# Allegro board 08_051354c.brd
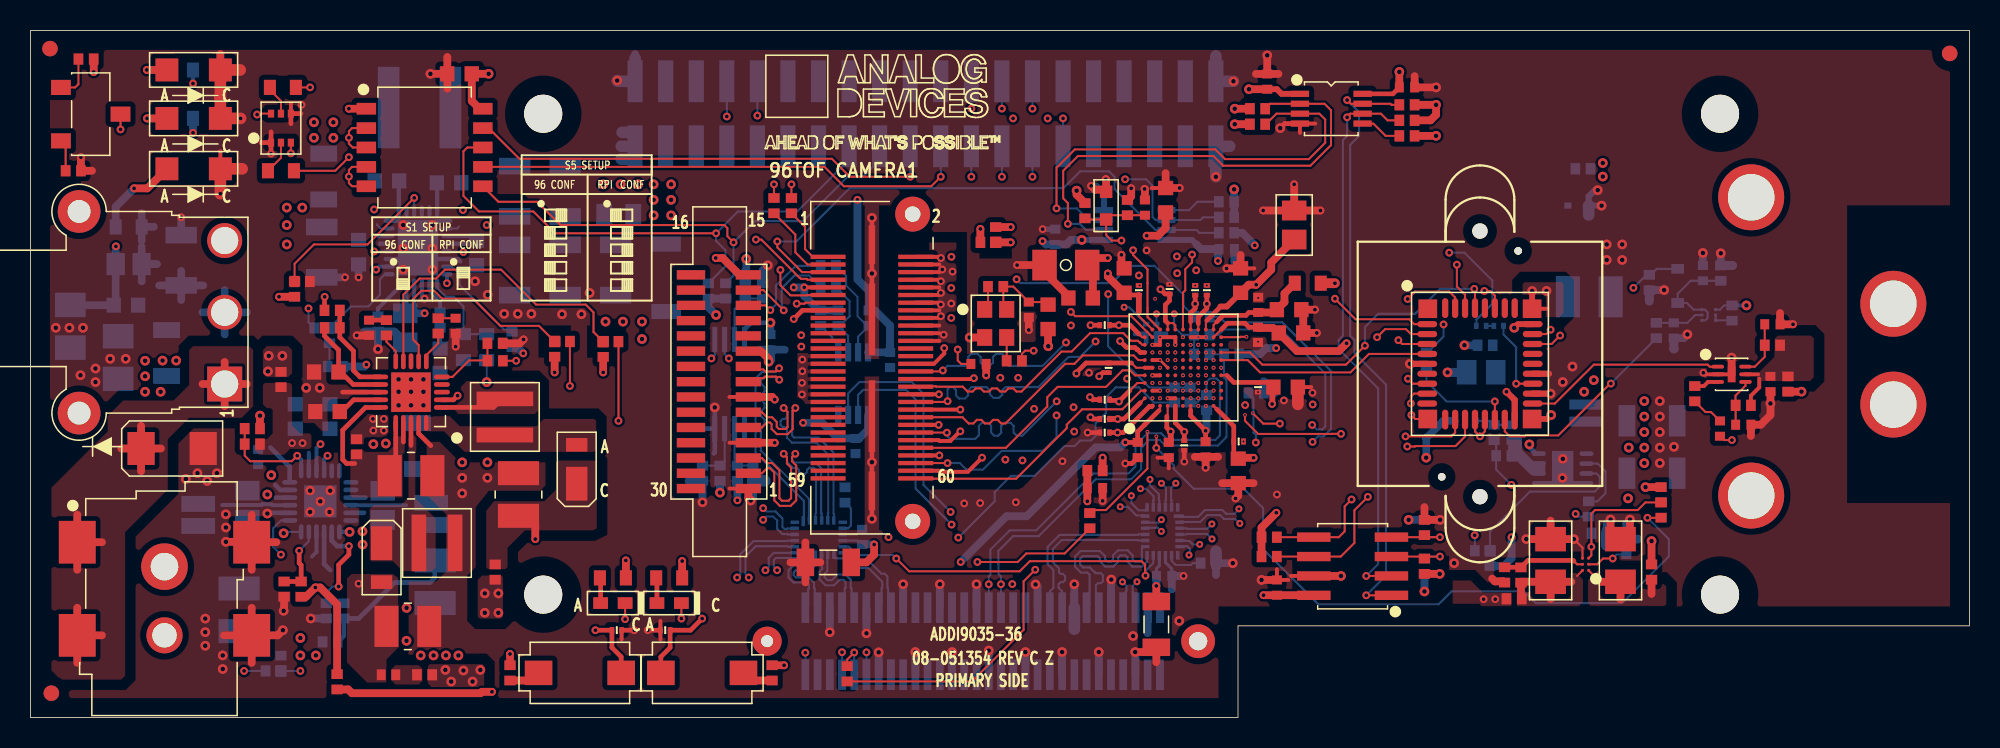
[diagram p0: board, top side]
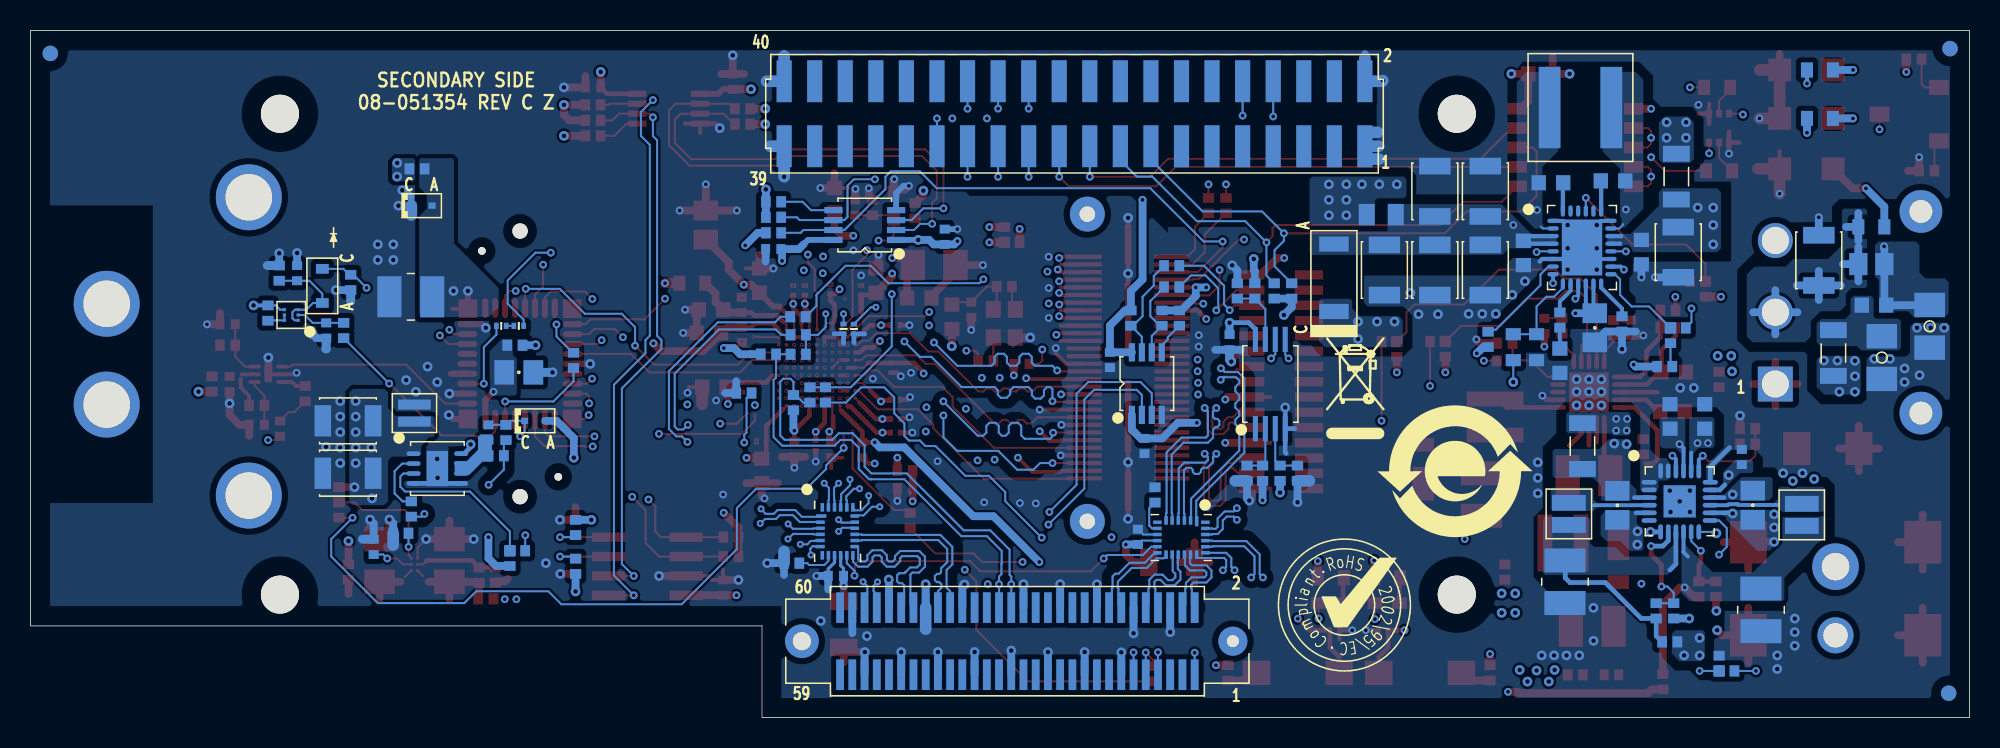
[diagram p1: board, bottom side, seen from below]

Outline 126.86 x 45 mm; copper layers: TOP, L2_GND, L3_SIG, L4_GND, L5_PWR, L6_PWR, L7_GND, L8_SIG, L9_GND, BOTTOM. Coordinates in mm from the lower left corner of the outline.
Outline path: 0,45 126.86,45 126.86,6 79,6 79,0 0,0 0,45

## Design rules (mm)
constraint set DEFAULT: min track width 0.203, pair gap 0.203
net group CLK_DATA_MISIPI: nets CLK_N CLK_P DATA0_N DATA0_P DATA1_N DATA1_P
net group LD1_LD4: nets LD1 LD2 LD3 LD4
net group MIPI_CSI0: nets MIPI_CSI0_CLK_N MIPI_CSI0_CLK_P MIPI_CSI0_DATA0_N MIPI_CSI0_DATA0_P MIPI_CSI0_DATA1_N MIPI_CSI0_DATA1_P
net group MIPI_CSI1: nets MIPI_CSI1_CLK_M MIPI_CSI1_CLK_P MIPI_CSI1_DATA0_M MIPI_CSI1_DATA0_P MIPI_CSI1_DATA1_M MIPI_CSI1_DATA1_P
net group RPI_DATA_P1_CONN: nets RPI_CLKN RPI_CLKP RPI_DATA0N RPI_DATA0P RPI_DATA1N RPI_DATA1P
net group RPI_SRS: nets RPI_SRS_CLKN RPI_SRS_CLKP RPI_SRS_DATA0N RPI_SRS_DATA0P RPI_SRS_DATA1N RPI_SRS_DATA1P
net group TAL1_TAL4: nets TAL1 TAL2 TAL3 TAL4

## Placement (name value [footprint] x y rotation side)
A1  ADA4800ACPZ  [UQFN6_1_6X1_6PAD0_5X1_05]  111.3 22.48 270 top
C1  2.2UF  [C1206]  73.66 6.1 90 top
C2  0.1uF  [C0201]  73.67 25.45 270 bottom
C3  4.7UF  [C0805H60]  14.18 13.91 90 bottom
C4  4.7UF  [C0805H60]  23.04 13.89 270 bottom
C5  0.1UF  [C0402]  65.31 26.71 270 top
C6  4.7uF  [C0603]  74.27 33.88 90 top
C7  0.1UF  [C0402]  69.64 15.03 0 top
C8  0.1uF  [C0201]  72.99 25.45 270 bottom
C9  0.1UF  [C0402]  14.89 17.06 270 bottom
C10  4.7uF  [C0603]  68.7 27.48 180 top
C11  4.7uF  [C0603]  79.17 28.62 90 top
C12  4.7uF  [C0603]  82.47 25.19 0 top
C13  1UF  [C0805H53]  82.68 32.26 90 top
C14  0.1uF  [C0201]  70.53 22.9 270 top
C15  0.1UF  [C0402]  80.31 25.06 270 top
C16  0.1uF  [C0201]  70.28 20.82 180 top
C17  0.1uF  [C0201]  76.96 27.98 90 top
C18  1000PF  [C0402]  107.51 25.35 270 bottom
C19  0.1uF  [C0201]  75.49 17.82 270 top
C20  4.7uF  [C0603]  82.34 26.71 180 top
C21  0.1UF  [C0402]  110.54 18.92 270 top
C22  0.1uF  [C0201]  80.31 21.63 270 top
C23  0.1uF  [C0201]  70.28 18.66 180 top
C24  0.1UF  [C0402]  62.02 23.16 0 top
C25  0.1uF  [C0201]  79.04 18.08 0 top
C26  0.1uF  [C0201]  70.28 25.7 180 top
C27  0.1UF  [C0402]  80.32 27.03 90 top
C28  0.1uF  [C0201]  72.51 27.98 90 top
C29  0.1UF  [C0402]  113.97 25.76 180 top
C30  0.01uF  [C0402]  109.42 29.11 90 bottom
C31  0.1uF  [C0201]  70.28 19.55 180 top
C33  0.1UF  [C0402]  76.88 17.57 270 top
C35  0.1uF  [C0603]  27.38 35.03 180 bottom
C37  4.7uF  [C0805H60]  24.51 25.53 90 bottom
C38  0.1uF  [C0603]  23.32 35.15 180 bottom
C41  10uF  [C1210-2]  24.89 15.84 0 top
C42  22UF  [C1210H106]  9.86 29.95 90 bottom
C43  1UF  [C0603]  19.35 22.63 180 top
C44  22UF  [C1210H106]  106.09 16 0 bottom
C45  1UF  [C0603]  19.59 19.72 90 bottom
C46  1UF  [C0603]  17.32 19.72 90 bottom
C47  10uF  [C1210-2]  26.46 8.89 270 bottom
C48  10uF  [C1210-2]  13.64 7.05 270 bottom
C49  10UF  [C1206H71]  2.6 25.62 90 bottom
C50  10UF  [C1206H71]  5.73 23.58 90 bottom
C51  10uF  [C1210-2]  101.98 27.56 0 bottom
C52  0.1UF  [C0402]  48.41 24.59 270 bottom
C53  1uF  [C0402]  72.44 17.52 90 top
C54  1uF  [C0402]  74.47 17.52 270 top
C55  0.10UF  [C0508H28]  101.74 19.94 90 bottom
C56  10NF  [C0402]  74.17 9.27 180 bottom
C57  1uF  [C0402]  72.91 33.4 270 top
C58  0.1uF  [C0201]  76.2 27.98 90 top
C59  0.033uF  [C0402]  96.9 18.67 90 bottom
C60  0.1uF  [C0201]  74.52 28.06 90 top
C61  10UF  [C1206H71]  67.74 29.64 180 top
C62  0.1UF  [C0402]  113.84 21.84 90 top
C63  0.1UF  [C0402]  80.91 41.66 270 top
C64  22UF  [C1210H106]  106.09 19.43 0 bottom
C65  0.1UF  [C0402]  112.06 19.18 0 top
C66  1UF  [C0603]  19.43 20.04 180 top
C67  0.1uF  [C0603]  28.07 42.16 0 top
C68  0.1UF  [C0402]  90.06 41.27 0 top
C69  0.1UF  [C0402]  81.55 8.51 270 top
C70  0.1UF  [C0402]  67.04 31.49 270 bottom
C71  10uF  [C1210-2]  24.68 5.97 0 top
C72  0.047UF  [C0402]  27.81 25.65 270 top
C73  0.01uF  [C0201]  96.06 25.65 0 bottom
C74  0.047UF  [C0402]  22.14 25.53 270 top
C75  0.1UF  [C0402]  78.26 30.68 0 bottom
C76  4.7UF  [C0805H60]  94.92 22.61 180 bottom
C77  0.01uF  [C0603]  79.02 16.15 90 top
C78  10uF  [C1210-2]  31.92 14.61 90 top
C79  2.2uF  [C1206H37]  104.03 10.29 90 top
C80  1000PF  [C0402]  104.41 11.18 90 bottom
C81  2.2uF  [C1206H37]  99.45 10.29 90 top
C82  0.01uF  [C0603]  82.12 21.64 180 top
C83  0.01uF  [C0603]  71.55 28.62 270 top
C84  0.01uF  [C0201]  38.35 5.71 0 top
C85  0.01uF  [C0201]  41.53 5.71 180 top
C86  2.2UF  [C1206]  52.2 10.16 0 top
C87  10NF  [C0402]  54.41 11.84 270 bottom
C88  0.1UF  [C0402]  53.98 17.78 90 bottom
C89  0.1UF  [C0402]  56.24 23.42 270 bottom
C90  47UF  [C1210H106]  38.28 29.31 270 bottom
C91  560pF  [C0603]  26.8 23.37 90 bottom
C92  47UF  [C1210H106]  34.98 34.47 90 bottom
C93  47UF  [C1210H106]  34.98 29.31 270 bottom
C94  47UF  [C1210H106]  31.67 34.47 90 bottom
C95  47UF  [C1210H106]  31.67 29.31 270 bottom
C96  1UF  [C0603]  29.18 30.43 270 bottom
C97  1UF  [C0603]  21.46 30.48 270 bottom
C98  22UF  [C1210H106]  19.05 30.48 270 bottom
D1  SMAJ5.0A  [DO214AC]  9.26 17.62 0 top
D2  PMEG3030EP,115  [SOD128]  41.58 28.8 90 bottom
D4  RB521S30T1G  [SOD523]  93.85 19.43 180 bottom
D5  1SS355VMTE-17  [SOD323-4]  107.77 28.27 270 bottom
D6  RB521S30T1G  [SOD523]  101.27 33.53 180 bottom
D8  DFLS240-7  [DSML110W70H39]  22.97 10.47 270 top
D9  DFLS240-7  [DSML110W70H39]  35.73 16.26 90 top
DS1  CMD15-21UGC/TR8 (green)  [LED1206]  10.67 35.94 180 top
DS2  CMD15-21UGC/TR8 (green)  [LED1206]  10.67 39.24 180 top
DS3  CMD15-21UGC/TR8 (green)  [LED1206]  10.67 42.42 180 top
DS4  APT1608LVBC/D  [LED0603]  38.1 7.49 180 top
DS5  APT1608LSECK/J3-PRV  [LED0603]  41.78 7.49 180 top
E1  60OHM AT 100MEGHZ  [L0603]  66.57 26.24 270 top
E2  22OHM AT 100MEGHZ  [L0805]  6.42 29.7 180 bottom
E3  30OHM  [L0603]  6.24 27.01 0 bottom
E4  470OHMS AT 100MEGHZ  [L0402]  23.42 2.79 0 top
L1  4.7uH  [LSML250W258H240]  25.45 39.95 180 bottom
L2  1uH  [LSML75W79H39]  10.97 13.27 90 bottom
L3  1uH  [LSML75W79H39]  26.21 13.34 90 bottom
L8  4.7uH  [LSMSQ157H122]  26.59 11.43 180 top
L9  4.7uH  [LSMSQ157H122]  31.03 19.68 270 top
LD_EN1  0  [R0402]  49.78 33.53 90 top
LD_EN2  0  [R0402]  48.64 33.53 90 top
NOREF  -  []  -176.26 -281.43 0 top
NOREF#2  -  []  126.86 6 0 top
NOREF#3  -  []  0 0 0 top
NOREF#4  -  [unnamed#2]  125.57 43.5 90 top
NOREF#5  -  []  281.83 80.52 0 top
NOREF#6  -  []  -125.84 190.5 0 top
NOREF#7  -  []  57.78 56.26 0 top
NOREF#8  -  []  -10.16 55.16 0 top
NOREF#9  -  [unnamed#3]  94.83 23.16 270 top
NOREF#10  -  [unnamed#2]  112.58 34.08 90 top
NOREF#11  -  []  0 0 0 top
NOREF#12  -  []  0 45 0 top
NOREF#13  -  []  0 45 0 top
NOREF#14  -  [unnamed#2]  33.54 8.05 0 top
NOREF#15  -  [unnamed#2]  110.54 8.05 0 top
NOREF#16  -  [unnamed#2]  121.88 20.5 90 top
NOREF#17  -  [unnamed#2]  110.54 39.55 0 top
NOREF#18  -  []  137.02 55.16 0 top
NOREF#19  -  []  79 0 0 top
NOREF#20  -  []  8.76 5.38 0 top
NOREF#21  -  [unnamed#2]  33.54 39.55 0 top
NOREF#22  -  [unnamed#2]  112.58 14.54 90 top
NOREF#23  -  []  332.25 207.39 0 top
NOREF#24  -  []  -176.26 -281.43 0 top
NOREF#25  -  [unnamed#2]  1.36 1.59 90 top
NOREF#26  -  []  222.6 -72.3 0 top
NOREF#27  -  []  -176.26 -281.43 0 top
NOREF#28  -  []  79 0 90 top
NOREF#29  -  []  8.76 5.38 0 top
NOREF#30  -  [unnamed#2]  1.27 43.81 90 top
NOREF#31  -  []  79 6 0 top
NOREF#32  -  [unnamed#2]  121.88 27.1 90 top
NOREF#33  -  []  126.86 45 270 bottom
NOREF#34  -  []  126.86 6 180 bottom
NOREF#35  -  []  33.66 16.13 180 bottom
NOREF#36  -  []  79 6 0 bottom
NOREF#37  -  []  0 45 0 bottom
NOREF#38  -  []  40.39 18.29 180 bottom
NOREF#39  -  []  40.89 7.37 180 bottom
NOREF#40  -  []  -10.16 -10.16 180 bottom
NOREF#41  -  []  79 0 180 bottom
NOREF#42  -  [unnamed#2]  1.36 1.59 90 bottom
NOREF#43  -  [unnamed#2]  1.27 43.81 90 bottom
NOREF#44  -  [unnamed#2]  125.57 43.5 90 bottom
NOREF#45  -  []  0 0 90 bottom
P1  1-1734248-5  [CNTE1-1734248-5]  45.09 22 90 top
P3  61083-063402LF  [CNFCI61083-063402]  62.29 5 0 bottom
P4  87759-4014  [CNSMMHDR2X20L1571W157H272]  58.55 39.55 0 bottom
P21  QSH-030-01-L-D-A  [CNHDR2X30H202]  55.05 22.91 270 top
P31  PJ-002AH-SMT-TR  [CNCUI-PJ-002A_A]  8.76 7.78 0 top
Q1  DST847BPDP6-7  [SOT-963]  109.8 26.37 90 bottom
Q2  BC847CDW1T1G  [SC70]  16.38 38.61 0 top
R1  10K  [R0402]  63.15 28.22 0 top
R2  49.9  [R0402]  80.19 21.25 180 bottom
R3  0  [R0402]  76.63 25.06 180 bottom
R4  0  [R0402]  51.69 26.16 270 bottom
R5  0  [R0402]  101.94 13.66 90 bottom
R6  0  [R0402]  76.63 23.79 180 bottom
R7  47  [R0402]  106.37 25.35 90 bottom
R8  0  [R0402]  30.4 9.53 270 top
R9  0  [R0402]  114.98 21.84 90 top
R10  0  [R0603]  83.57 28.45 180 top
R11  536K  [R0603]  29.84 24.26 90 bottom
R12  102K  [R0603]  28.32 24.26 270 bottom
R13  100K  [R0402]  26.8 26.04 90 bottom
R14  162K  [R0402]  22.73 25.78 270 bottom
R15  100K  [R0402]  19.94 22.99 180 bottom
R16  100K  [R0402]  31.5 24.77 90 bottom
R17  0  [R1206]  25.32 17.78 270 bottom
R18  10K  [R0402]  14.51 18.92 180 top
R19  26.7K  [R0402]  14.51 17.91 0 top
R20  29.4K  [R0402]  19.35 6.99 270 bottom
R21  95.3K  [R0402]  20.49 6.99 270 bottom
R22  0  [R0402]  20.06 2.34 270 top
R23  19.1K  [R0402]  16.59 8.41 270 top
R24  0  [R0402]  78.25 33.78 180 bottom
R25  0  [R0805]  38.48 32.94 180 bottom
R26  1K  [R0402]  111.32 26.49 270 bottom
R27  5.1K  [R0402]  110.59 29.11 90 bottom
R28  0  [R0402]  74.85 21.13 90 bottom
R29  1MEG  [R0402]  105.91 28.5 270 bottom
R30  115K  [R0402]  17.7 8.41 270 top
R31  120K  [R0402]  113.97 24.38 0 top
R32  0  [R0402]  19.6 4.95 180 bottom
R33  249K  [R0402]  112.06 20.45 0 top
R34  0  [R0402]  16.38 22.14 90 top
R35  0  [R0402]  34.29 24.13 90 top
R36  0  [R0402]  2.79 35.81 180 top
R37  300  [R0603]  38.1 9.14 180 top
R38  10K  [R0402]  102.63 12.06 0 bottom
R39  0  [R1206]  19.18 35.43 270 bottom
R40  49.9  [R0402]  96.39 17.14 0 bottom
R41  0  [R0402]  75.87 21.13 90 bottom
R42  0  [R0402]  95.76 18.67 270 bottom
R43  10K  [R0402]  76.94 20.63 90 bottom
R44  0  [R0402]  21.34 17.73 270 top
R45  10K  [R0402]  78.58 23.8 180 bottom
R46  147K  [R0402]  19.73 25.53 0 top
R47  0  [R0402]  45.11 16 270 bottom
R48  137K  [R0402]  30.39 24.51 0 top
R49  1.2MEG  [R0402]  19.73 26.67 180 top
R50  24.9K  [R0402]  26.67 25.65 90 top
R51  6.8K  [R0402]  23.29 25.53 90 top
R52  2.37MEG  [R0402]  30.4 23.37 0 top
R53  0  [R0402]  25.78 2.79 0 top
R54  0  [R0402]  43.96 16 90 bottom
R55  0  [R0402]  46.76 27.94 90 bottom
R56  0  [R0402]  106.06 9.53 270 top
R57  14.3K  [R0402]  96.44 9.34 270 top
R58  93.1K  [R0402]  97.51 9.33 270 top
R59  0  [R0402]  97.07 7.77 180 top
R60  0  [R0402]  47.9 27.94 270 bottom
R61  10K  [R0402]  44.34 27.94 270 bottom
R62  0  [R0402]  46.25 16 270 bottom
R63  0  [R0402]  47.27 16 90 bottom
R64  10K  [R0402]  45.49 27.94 270 bottom
R65  0  [R0402]  69.64 16.17 0 top
R66  4.7  [R0402]  91.33 23.39 270 bottom
R67  22K  [R0402]  80.28 38.86 180 top
R68  22K  [R0402]  80.28 39.88 180 top
R69  4.7  [R0201]  94.92 25.65 0 bottom
R70  0  [R0402]  101.57 35.94 0 bottom
R71  0  [R0402]  95.17 24.38 180 bottom
R72  45.3K  [R0402]  68.99 33.2 90 top
R73  45.3K  [R0402]  71.77 33.4 270 top
R74  4.7K  [R0402]  90.06 39.12 180 top
R75  300  [R0603]  41.78 9.14 180 top
R76  0  [R0402]  108.89 21.21 270 top
R77  1K  [R0402]  31.37 2.92 270 top
R78  10K  [R0603]  16.38 35.81 180 top
R79  10K  [R0603]  16.51 41.27 180 top
R80  1K  [R0402]  48.51 2.92 270 top
R81  4.7K  [R0402]  52.83 26.16 90 bottom
R82  4.7K  [R0402]  90.06 40.13 180 top
R83  4.7K  [R0402]  54.86 26.16 90 bottom
R84  0  [R0402]  53.29 14.58 90 bottom
R85  0  [R0402]  37.47 24.12 90 top
R86  10K  [R0402]  81.04 11.81 0 top
R87  10K  [R0402]  81.04 10.54 0 top
R88  0  [R0402]  76.65 26.25 0 bottom
R89  0  [R0402]  69.31 12.89 270 top
R90  0  [R0402]  77.06 10.11 180 bottom
R91  0  [R0402]  3.63 43.13 0 top
R92  0  [R0402]  34.79 24.63 0 top
R93  4.7K  [R0402]  78.25 32.77 0 bottom
R94  4.7K  [R0402]  78.25 31.75 0 bottom
R95  0  [R1206]  8.9 23.88 270 bottom
R96  0  [R0402]  37.97 24.62 0 top
R97  0  [R0402]  15.88 3.05 0 bottom
R98  0  [R0402]  52.2 29.59 180 bottom
R99  0  [R0402]  16.38 3.55 90 bottom
R100  150  [R0603]  6.42 32.14 0 bottom
R101  0  [R0402]  90.06 38.1 0 top
R102  0  [R0402]  91.2 12.45 90 bottom
R103  0  [R0402]  91.2 12.45 270 top
R104  680  [R0603]  9.78 39.24 180 bottom
R105  0  [R0402]  91.2 9.91 270 bottom
R106  0  [R0402]  91.2 9.91 90 top
R107  0  [R0402]  17.27 28.06 90 top
R108  220  [R0603]  9.78 42.42 0 bottom
R109  0  [R0402]  52.2 28.19 180 bottom
R110  22  [R0402]  64.36 23.37 0 top
R111  0  [R0402]  106.68 14.59 270 top
R112  0  [R0402]  17.77 28.56 0 top
R113  22  [R0402]  53.43 2.86 90 top
R114  0  [R0402]  106.68 13.59 270 top
R115  0  [R0402]  19.56 25.02 90 bottom
R116  0  [R0402]  19.06 25.52 180 bottom
R117  0  [R0402]  95.5 10.42 90 bottom
R118  0  [R0402]  95 10.92 180 bottom
R119  0  [R0402]  63.15 31.62 90 top
R120  0  [R0402]  62.65 31.12 0 top
RT1  100K  [R0603H35]  70.37 33.53 270 top
S1  CAS-120TB  [SWSML213W98H98]  3.94 39.52 270 top
S2  MS12ASW30  [SWTHL500W272H280]  12.7 21.84 90 top
S3  SKQMBBE010  [SWSML236W138H197]  35.94 2.92 0 top
S4  SKQMBBE010  [SWSML236W138H197]  43.94 2.92 0 top
S5  4.16131E+11  [SWSML291W220H83]  25.78 37.34 270 top
U1  MN34906BL  [QFN38_7_8X7_4]  94.83 23.16 270 top
U2  LTC3119EUFD#TRPBF  [QFN28_5X4_PAD3_65X2_65]  25.35 30.78 270 bottom
U3  ADP5023ACPZ  [QFN24_4X4_PAD2_1X2_1]  18.96 14.16 270 bottom
U4  ADDI9036BCBZRL  [WLCSP117_A]  75.4 22.91 0 top
U5  AT24CM01-XHM-B  [TSSOP8]  45.74 21.84 180 bottom
U6  FAN3121TMPX  [MLP8_3X3_PAD2_3X1_4]  100.24 16.31 270 bottom
U7  FSA642UMX  [QFN24_3_4X2_5]  74.05 12.19 270 bottom
U8  PCA9517ADMR2G  [MSOP8_ALT]  85.1 39.88 270 top
U9  PCA9517ADMR2G  [MSOP8_ALT]  72.28 32.26 90 bottom
U10  ADP5071ACPZ  [QFN20_4X4_PAD2_6X2_6]  24.89 21.31 90 top
U11  FSA642UMX  [QFN24_3_4X2_5]  51.56 11.79 0 bottom
U12  ADP7112ACBZ-1.2-R7  [WLCSP6_B]  101.74 10.03 90 top
U13  ADT7410TRZ  [SO8]  86.5 9.91 90 top
U14  PCA9517ADMR2G  [MSOP8_ALT]  53.82 21.87 180 bottom
Y1  45.000000MEGHZ  [YSML98W79H35]  63.15 25.81 270 top

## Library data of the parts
A1 = ADA4800: User Part Number: UPN; Tolerance: N/A; alternate symbols: (); part number: ADA4800_SM-ADA4800ACPZ,E012130,UQFN6_1_6X1_6PAD0_5X1_05; tolerance: N/A
C1 C86 = CAP: User Part Number: UPN; Tolerance: 10; alternate symbols: (); part number: CAP_SM-2.2UF,16V,10,E033858,C1206; tolerance: 10
C2 C8 C14 C16 C17 C19 C22 C23 C25 C26 C28 C31 C58 C60 = CAP: Tolerance: 10; User Part Number: UPN; alternate symbols: (); part number: CAP_SM-0.1UF,6.3V,10,E011567,C0201; tolerance: 10
C3 C4 C76 = CAP: Tolerance: 10; User Part Number: UPN; alternate symbols: (); part number: CAP_SM-4.7UF,25V,10,E033894,C0805H60; tolerance: 10
C5 C7 C9 C15 C21 C24 C27 C29 C33 C52 C62 C63 C65 C68-C70 C75 C88 C89 = CAP: User Part Number: UPN; Tolerance: 10; alternate symbols: (); part number: CAP_SM-0.1UF,16V,10,E028141,C0402; tolerance: 10
C6 C10-C12 C20 = CAP: User Part Number: UPN; Tolerance: 10; alternate symbols: (); part number: CAP_SM-4.7UF,16V,10,E022190,C0603; tolerance: 10
C13 = CAP: Tolerance: 10; User Part Number: UPN; alternate symbols: (); part number: CAP_SM-1UF,35V,10,E035216,C0805H53; tolerance: 10
C18 = CAP: User Part Number: UPN; Tolerance: 10; alternate symbols: (); part number: CAP_SM-1000PF,50V,10,E020689,C0402; tolerance: 10
C30 = CAP: User Part Number: UPN; Tolerance: 5; alternate symbols: (C0402L_ALT); part number: CAP_SM-0.01UF,25V,5,E020410,C0402; tolerance: 5
C35 C38 = CAP: User Part Number: UPN; Tolerance: 10; alternate symbols: (); part number: CAP_SM-0.1UF,50V,10,E011865,C0603; tolerance: 10
C37 = CAP: Tolerance: 10; User Part Number: UPN; alternate symbols: (); part number: CAP_SM-4.7UF,10V,10,E019528,C0805H60; tolerance: 10
C41 C47 C48 C51 C71 C78 = CAP: Tolerance: 10; User Part Number: UPN; alternate symbols: (); part number: CAP_SM-10UF,50V,10,E022361,C1210-2; tolerance: 10
C42 C44 C64 C98 = CAP: Tolerance: 10; User Part Number: UPN; alternate symbols: (); part number: CAP_SM-22UF,25V,10,E025745,C1210H106; tolerance: 10
C43 C45 C46 C66 = CAP: User Part Number: UPN; Tolerance: 10; alternate symbols: (); part number: CAP_SM-1UF,25V,10,E033468,C0603; tolerance: 10
C49 C50 C61 = CAP: Tolerance: 10; User Part Number: UPN; alternate symbols: (); part number: CAP_SM-10UF,25V,10,E022363,C1206H71; tolerance: 10
C53 C54 C57 = CAP: User Part Number: UPN; Tolerance: 10; alternate symbols: (); part number: CAP_SM-1UF,6.3V,10,E011561,C0402; tolerance: 10
C55 = CAP: Tolerance: 20; User Part Number: UPN; alternate symbols: (); part number: CAP_SM-0.10UF,25V,20,E025747,C0508H28; tolerance: 20
C56 C87 = CAP: User Part Number: UPN; Tolerance: 10; alternate symbols: (); part number: CAP_SM-10NF,25V,10,E033465,C0402; tolerance: 10
C59 = CAP: User Part Number: UPN; Tolerance: 10; alternate symbols: (); part number: CAP_SM-0.033UF,50V,10,E019776,C0402; tolerance: 10
C67 = CAP: User Part Number: UPN; Tolerance: 10; alternate symbols: (); part number: CAP_SM-0.1UF,16V,10,E011547,C0603; tolerance: 10
C72 C74 = CAP: User Part Number: UPN; Tolerance: 10; alternate symbols: (); part number: CAP_SM-0.047UF,25V,10,E025704,C0402; tolerance: 10
C73 C84 C85 = CAP: Tolerance: 10; User Part Number: UPN; alternate symbols: (); part number: CAP_SM-0.01UF,10V,10,E007201,C0201; tolerance: 10
C77 C82 C83 = CAP: User Part Number: UPN; Tolerance: 5; alternate symbols: (); part number: CAP_SM-0.01UF,25V,5,E012400,C0603; tolerance: 5
C79 C81 = CAP: Tolerance: 10; User Part Number: UPN; alternate symbols: (); part number: CAP_SM-2.2UF,50V,10,E020593,C1206H37; tolerance: 10
C80 = CAP: User Part Number: UPN; Tolerance: 10; alternate symbols: (); part number: CAP_SM-1000PF,25V,10,E025706,C0402; tolerance: 10
C90 C92-C95 = CAP: Tolerance: 10; User Part Number: UPN; alternate symbols: (); part number: CAP_SM-47UF,16V,10,E038427,C1210H106; tolerance: 10
C91 = CAP: User Part Number: UPN; Tolerance: 10; alternate symbols: (); part number: CAP_SM-560PF,50V,10,E005344,C0603; tolerance: 10
C96 C97 = CAP: User Part Number: UPN; Tolerance: 10; alternate symbols: (); part number: CAP_SM-1UF,25V,10,E033832,C0603; tolerance: 10
D1 = DIO: User Part Number: UPN; Tolerance: 5; alternate symbols: (); part number: DIO_SM-SMAJ5.0A,N/A,5,E020098,DO214AC; tolerance: 5
D2 = DIOSCHOTTKY: User Part Number: UPN; Tolerance: N/A; alternate symbols: (); part number: DIOSCHOTTKY_SM-PMEG3030EP,115,30V,N/A,E033206,SOD128; tolerance: N/A
D4 D6 = DIO: Tolerance: N/A; User Part Number: UPN; alternate symbols: (); part number: DIO_SM-RB521S30T1G,30V,N/A,E011362,SOD523; tolerance: N/A
D5 = DIO: Tolerance: N/A; User Part Number: UPN; alternate symbols: (); part number: DIO_SM-1SS355VMTE-17,80V,N/A,E027000,SOD323-4; tolerance: N/A
D8 D9 = DIOSCHOTTKY: Tolerance: N/A; User Part Number: UPN; alternate symbols: (); part number: DIOSCHOTTKY_SM-DFLS240-7,40V,N/A,E019969,DSML110W70H39; tolerance: N/A
DS1-DS3 = DIOLED: Tolerance: N/A; User Part Number: UPN; alternate symbols: (); part number: DIOLED_SM-CMD15-21UGC/TR8 (GREEN),2.1V,N/A,E012771,LED1206; tolerance: N/A
DS4 = DIOLED: Tolerance: N/A; User Part Number: UPN; alternate symbols: (); part number: DIOLED_SM-APT1608LVBC/D,2.65V,N/A,E033357,LED0603; tolerance: N/A
DS5 = DIOLED: Tolerance: N/A; User Part Number: UPN; alternate symbols: (); part number: DIOLED_SM-APT1608LSECK/J3-PRV,1.8V,N/A,E030191,LED0603; tolerance: N/A
E1 = FERRITE: User Part Number: UPN; Tolerance: 25; alternate symbols: (); part number: FERRITE_SM-60OHM AT 100MEGHZ,25,E029937,L0603; tolerance: 25
E2 = FERRITE: User Part Number: UPN; Tolerance: 25; alternate symbols: (); part number: FERRITE_SM-22OHM AT 100MEGHZ,25,E029266,L0805; tolerance: 25
E3 = FERRITE: User Part Number: UPN; Tolerance: 10OHM; alternate symbols: (); part number: FERRITE_SM-30OHM,10OHM,E027025,L0603; tolerance: 10OHM
E4 = FERRITE: User Part Number: UPN; Tolerance: 25; alternate symbols: (); part number: FERRITE_SM-470OHMS AT 100MEGHZ,25,E027133,L0402; tolerance: 25
L1 = IND: Tolerance: 20; User Part Number: UPN; alternate symbols: (); part number: IND_SM-4.7UH,20,E022875,LSML250W258H240; tolerance: 20
L2 L3 = IND: Tolerance: 20; User Part Number: UPN; alternate symbols: (); part number: IND_SM-1UH,20,E015752,LSML75W79H39; tolerance: 20
L8 L9 = IND: User Part Number: UPN; Tolerance: 20; alternate symbols: (); part number: IND_SM-4.7UH,20,E013623,LSMSQ157H122; tolerance: 20
LD_EN1 LD_EN2 = RESJMPRSHRT: User Part Number: UPN; Tolerance: N/R; alternate symbols: (); part number: RESJMPRSHRT_SM-0,E003438,N/RW,N/R,R0402; tolerance: N/R
P1 = CN30P_V2: User Part Number: UPN; Tolerance: N/A; alternate symbols: (); part number: CN30P_V2_SM-1-1734248-5,E033905,CNTE1-1734248-5; tolerance: N/A
P3 = CN60P_ODD_EVEN: User Part Number: UPN; Tolerance: N/A; alternate symbols: (); part number: CN60P_ODD_EVEN_SM-61083-063402LF,E033470,CNFCI61083-063402; tolerance: N/A
P4 = CN40P_V2: User Part Number: UPN; Tolerance: N/A; alternate symbols: (); part number: CN40P_V2_SM-87759-4014,E033485,CNSMMHDR2X20L1571W157H272; tolerance: N/A
P21 = CN60P_ODD_EVEN_4GND: User Part Number: UPN; Tolerance: N/A; alternate symbols: (CNHDR2X30H202_ALT); part number: CN60P_ODD_EVEN_4GND_SM-QSH-030-01-L-D-A,E014016,CNHDR2X30H202; tolerance: N/A
P31 = CN4P_V6: User Part Number: UPN; Tolerance: N/A; alternate symbols: (); part number: CN4P_V6_SM-PJ-002AH-SMT-TR,E022246,CNCUI-PJ-002A_A; tolerance: N/A
Q1 = TRANNPN_PNP: Tolerance: N/A; User Part Number: UPN; alternate symbols: (); part number: TRANNPN_PNP_SM-DST847BPDP6-7,E028630,SOT-963; tolerance: N/A
Q2 = TRANBC84XXDW: Tolerance: N/A; User Part Number: UPN; alternate symbols: (); part number: TRANBC84XXDW_SM-BC847CDW1T1G,E011779,SC70; tolerance: N/A
R1 R18 R38 R43 R45 R61 R64 = RES: User Part Number: UPN; Tolerance: 1; alternate symbols: (R0402L,R0402L_ALT); part number: RES_SM-10K,E003751,1/10W,1,R0402; tolerance: 1
R2 R40 = RES: User Part Number: UPN; Tolerance: 0.1; alternate symbols: (R0402L,R0402L_ALT); part number: RES_SM-49.9,E005976,1/16W,0.1,R0402; tolerance: 0.1
R3-R6 R8 R9 R22 R24 R28 R32 R34-R36 R41 R42 R44 R47 R54-R56 R59 R60 R62 R63 R65 R70 R71 R76 R84 R85 R88-R92 R96-R99 R101-R103 R105-R107 R109 R111 R112 R114-R120 = RES: User Part Number: UPN; Tolerance: 5; alternate symbols: (R0402L,R0402L_ALT); part number: RES_SM-0,E003438,N/A,5,R0402; tolerance: 5
R7 = RES: User Part Number: UPN; Tolerance: 5; alternate symbols: (R0402L); part number: RES_SM-47,E017767,1/10W,5,R0402; tolerance: 5
R10 = RES: User Part Number: UPN; Tolerance: 5; alternate symbols: (R0603L); part number: RES_SM-0,E006826,1/10W,5,R0603; tolerance: 5
R11 = RES: User Part Number: UPN; Tolerance: 1; alternate symbols: (); part number: RES_SM-536K,E036012,1/10W,1,R0603; tolerance: 1
R12 = RES: User Part Number: UPN; Tolerance: 1; alternate symbols: (R0603L); part number: RES_SM-102K,E014965,1/10W,1,R0603; tolerance: 1
R13 R15 R16 = RES: User Part Number: UPN; Tolerance: 1; alternate symbols: (R0402L,R0402L_ALT); part number: RES_SM-100K,E003796,1/16W,1,R0402; tolerance: 1
R14 = RES: User Part Number: UPN; Tolerance: 1; alternate symbols: (); part number: RES_SM-162K,E035428,1/10W,1,R0402; tolerance: 1
R17 R39 R95 = RES: User Part Number: UPN; Tolerance: N/A; alternate symbols: (); part number: RES_SM-0,E014206,1/2W,N/A,R1206; tolerance: N/A
R19 = RES: User Part Number: UPN; Tolerance: 1; alternate symbols: (R0402L); part number: RES_SM-26.7K,E012976,1/16W,1,R0402; tolerance: 1
R20 = RES: User Part Number: UPN; Tolerance: 1; alternate symbols: (R0402L); part number: RES_SM-29.4K,E025783,1/10W,1,R0402; tolerance: 1
R21 = RES: User Part Number: UPN; Tolerance: 1; alternate symbols: (R0402L); part number: RES_SM-95.3K,E006343,1/16W,1,R0402; tolerance: 1
R23 = RES: User Part Number: UPN; Tolerance: 1; alternate symbols: (R0402L); part number: RES_SM-19.1K,E025171,1/10W,1,R0402; tolerance: 1
R25 = RES: User Part Number: UPN; Tolerance: N/A; alternate symbols: (R0805L); part number: RES_SM-0,E004152,1/10W,N/A,R0805; tolerance: N/A
R26 R77 R80 = RES: User Part Number: UPN; Tolerance: 1; alternate symbols: (R0402L,R0402L_ALT); part number: RES_SM-1K,E003763,1/10W,1,R0402; tolerance: 1
R27 = RES: User Part Number: UPN; Tolerance: 0.1; alternate symbols: (R0402L); part number: RES_SM-5.1K,E010267,1/16W,0.1,R0402; tolerance: 0.1
R29 = RES: User Part Number: UPN; Tolerance: 0.5; alternate symbols: (R0402L); part number: RES_SM-1MEG,E020373,1/16W,0.5,R0402; tolerance: 0.5
R30 = RES: User Part Number: UPN; Tolerance: 1; alternate symbols: (R0402L); part number: RES_SM-115K,E025179,1/10W,1,R0402; tolerance: 1
R31 = RES: User Part Number: UPN; Tolerance: 1; alternate symbols: (R0402L); part number: RES_SM-120K,E015615,1/10W,1,R0402; tolerance: 1
R33 = RES: User Part Number: UPN; Tolerance: 1; alternate symbols: (R0402L); part number: RES_SM-249K,E026055,1/16W,1,R0402; tolerance: 1
R37 R75 = RES: User Part Number: UPN; Tolerance: 1; alternate symbols: (R0603L); part number: RES_SM-300,E010157,1/10W,1,R0603; tolerance: 1
R46 = RES: User Part Number: UPN; Tolerance: 1; alternate symbols: (R0402L); part number: RES_SM-147K,E006339,1/16W,1,R0402; tolerance: 1
R48 = RES: User Part Number: UPN; Tolerance: 0.5; alternate symbols: (R0402L); part number: RES_SM-137K,E025681,1/16W,0.5,R0402; tolerance: 0.5
R49 = RES: User Part Number: UPN; Tolerance: 1; alternate symbols: (R0402L); part number: RES_SM-1.2MEG,E024939,1/16W,1,R0402; tolerance: 1
R50 = RES: User Part Number: UPN; Tolerance: 1; alternate symbols: (R0402L); part number: RES_SM-24.9K,E007443,1/16W,1,R0402; tolerance: 1
R51 = RES: User Part Number: UPN; Tolerance: 1; alternate symbols: (R0402L); part number: RES_SM-6.8K,E011558,1/10W,1,R0402; tolerance: 1
R52 = RES: User Part Number: UPN; Tolerance: 1; alternate symbols: (R0402L); part number: RES_SM-2.37MEG,E025742,1/16W,1,R0402; tolerance: 1
R53 = RES: User Part Number: UPN; Tolerance: 1; alternate symbols: (R0402L); part number: RES_SM-0,E010661,1/16W,1,R0402; tolerance: 1
R57 = RES: User Part Number: UPN; Tolerance: 1; alternate symbols: (R0402L); part number: RES_SM-14.3K,E025740,1/10W,1,R0402; tolerance: 1
R58 = RES: User Part Number: UPN; Tolerance: 1; alternate symbols: (R0402L); part number: RES_SM-93.1K,E025741,1/10W,1,R0402; tolerance: 1
R66 = RES: User Part Number: UPN; Tolerance: 5; alternate symbols: (R0402L); part number: RES_SM-4.7,E021865,1/10W,5,R0402; tolerance: 5
R67 R68 = RES: User Part Number: UPN; Tolerance: 1; alternate symbols: (R0402L); part number: RES_SM-22K,E018369,1/16W,1,R0402; tolerance: 1
R69 = RES: Tolerance: 5; User Part Number: UPN; alternate symbols: (); part number: RES_SM-4.7,E019116,1/20W,5,R0201; tolerance: 5
R72 R73 = RES: User Part Number: UPN; Tolerance: 1; alternate symbols: (R0402L); part number: RES_SM-45.3K,E019617,1/16W,1,R0402; tolerance: 1
R74 R81-R83 R93 R94 = RES: User Part Number: UPN; Tolerance: 1; alternate symbols: (R0402L,R0402L_ALT); part number: RES_SM-4.7K,E008190,1/10W,1,R0402; tolerance: 1
R78 R79 = RES: User Part Number: UPN; Tolerance: 1; alternate symbols: (R0603L); part number: RES_SM-10K,E003671,1/10W,1,R0603; tolerance: 1
R86 R87 = RES: User Part Number: UPN; Tolerance: 5; alternate symbols: (R0402L); part number: RES_SM-10K,E017176,1/10W,5,R0402; tolerance: 5
R100 = RES: User Part Number: UPN; Tolerance: 1; alternate symbols: (R0603L); part number: RES_SM-150,E003691,1/10W,1,R0603; tolerance: 1
R104 = RES: User Part Number: UPN; Tolerance: 1; alternate symbols: (R0603L); part number: RES_SM-680,E004249,1/16W,1,R0603; tolerance: 1
R108 = RES: User Part Number: UPN; Tolerance: 5; alternate symbols: (R0603L); part number: RES_SM-220,E020960,1/4W,5,R0603; tolerance: 5
R110 R113 = RES: User Part Number: UPN; Tolerance: 1; alternate symbols: (R0402L); part number: RES_SM-22,E008191,1/16W,1,R0402; tolerance: 1
RT1 = RESTHERM: Tolerance: 1; User Part Number: UPN; alternate symbols: (); part number: RESTHERM_SM-100K,E029946,0.1W,1,R0603H35; tolerance: 1
S1 = SWSPDT_V2: Tolerance: N/A; User Part Number: UPN; alternate symbols: (); part number: SWSPDT_V2_SM-CAS-120TB,E012554,SWSML213W98H98; tolerance: N/A
S2 = SWSPDT: User Part Number: UPN; Tolerance: N/A; alternate symbols: (); part number: SWSPDT_TH-MS12ASW30,E026754,SWTHL500W272H280; tolerance: N/A
S3 S4 = SWSPST2PIN_V3: Tolerance: N/A; User Part Number: UPN; alternate symbols: (); part number: SWSPST2PIN_V3_SM-SKQMBBE010,E026439,SWSML236W138H197; tolerance: N/A
S5 = SWSPST10PIN: Tolerance: N/A; User Part Number: UPN; alternate symbols: (); part number: SWSPST10PIN_SM-4.16131E+11,E021600,SWSML291W220H83; tolerance: N/A
U1 = MN34906BL: Tolerance: N/A; User Part Number: UPN; alternate symbols: (); part number: MN34906BL_SM-MN34906BL,E023780,QFN38_7_8X7_4; tolerance: N/A
U2 = LINLTC3119: User Part Number: UPN; Tolerance: N/A; alternate symbols: (); part number: LINLTC3119_SM-LTC3119EUFD#TRPBF,E029728,QFN28_5X4_PAD3_65X2_65; tolerance: N/A
U3 = ADP5023: Tolerance: N/A; User Part Number: UPN; alternate symbols: (); part number: ADP5023_SM-ADP5023ACPZ,E015738,QFN24_4X4_PAD2_1X2_1; tolerance: N/A
U4 = ADDI9036: User Part Number: UPN; Tolerance: N/A; alternate symbols: (); part number: ADDI9036_SM-ADDI9036BCBZRL,E033667,WLCSP117_A; tolerance: N/A
U5 = ICAT24CM01: Tolerance: N/A; User Part Number: UPN; alternate symbols: (); part number: ICAT24CM01_SM-AT24CM01-XHM-B,E027200,TSSOP8; tolerance: N/A
U6 = ICFAN3121: Tolerance: N/A; User Part Number: UPN; alternate symbols: (); part number: ICFAN3121_SM-FAN3121TMPX,E024221,MLP8_3X3_PAD2_3X1_4; tolerance: N/A
U7 U11 = ICFSA642: User Part Number: UPN; Tolerance: N/A; alternate symbols: (); part number: ICFSA642_SM-FSA642UMX,E033686,QFN24_3_4X2_5; tolerance: N/A
U8 U9 U14 = ICPCA9517A: Tolerance: N/A; User Part Number: UPN; alternate symbols: (MSOP); part number: ICPCA9517A_SM-PCA9517ADMR2G,E022571,MSOP8_ALT; tolerance: N/A
U10 = ADP5071: User Part Number: UPN; Tolerance: N/A; alternate symbols: (); part number: ADP5071_SM-ADP5071ACPZ,E023943,QFN20_4X4_PAD2_6X2_6; tolerance: N/A
U12 = ADP7112: User Part Number: UPN; Tolerance: N/A; alternate symbols: (); part number: ADP7112_SM-ADP7112ACBZ-1.2-R7,E024303,WLCSP6_B; tolerance: N/A
U13 = ADT7410: Tolerance: N/A; User Part Number: UPN; alternate symbols: (); part number: ADT7410_SM-ADT7410TRZ,E010871,SO8; tolerance: N/A
Y1 = XTALOSC4P_V3: Tolerance: N/A; User Part Number: UPN; alternate symbols: (); part number: XTALOSC4P_V3_SM-45.000000MEGHZ,E025786,YSML98W79H35; tolerance: N/A

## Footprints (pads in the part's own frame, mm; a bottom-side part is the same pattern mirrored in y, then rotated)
C0201
  rect 0.305x0.406 smd: 1(-0.318,0) 2(0.318,0)
C0402
  rect 0.584x0.66 smd: 1(-0.5,0) 2(0.5,0)
C0508H28
  rect 0.66x2.134 smd: 1(-0.56,0) 2(0.56,0)
C0603
  rect 0.94x0.991 smd: 1(-0.8,0) 2(0.8,0)
C0805H53
  rect 1.295x1.6 smd: 1(-0.953,0) 2(0.953,0)
C0805H60
  rect 1.295x1.6 smd: 1(-0.953,0) 2(0.953,0)
C1206
  rect 1.143x1.803 smd: 1(-1.5,0) 2(1.5,0)
C1206H37
  rect 1.6x2.007 smd: 1(-1.397,0) 2(1.397,0)
C1206H71
  rect 1.6x2.007 smd: 1(-1.397,0) 2(1.397,0)
C1210-2
  rect 1.575x2.692 smd: 1(-1.397,0) 2(1.397,0)
C1210H106
  rect 1.092x2.057 smd: 1(-1.646,0) 2(1.646,0)
CNCUI-PJ-002A_A
  round 3.048 hole 1.803 unplated: (0,2.1)
  round 2.362 hole 1.6 unplated: (0,-2.4)
  rect 2.413x2.794 smd: 1A(-5.707,3.7) 1B(-5.707,-2.4) 2(5.707,-2.4) 3(5.707,3.7)
CNFCI61083-063402
  round 1.905 hole 0.787 unplated: (-14.1,0)
  round 2.21 hole 1.194 unplated: (14.1,0)
  rect 0.508x2.007 smd: 1(-11.6,2.197) 2(-11.6,-2.197) 3(-10.8,2.197) 4(-10.8,-2.197) 5(-10,2.197) 6(-10,-2.197) 7(-9.2,2.197) 8(-9.2,-2.197) 9(-8.4,2.197) 10(-8.4,-2.197) 11(-7.6,2.197) 12(-7.6,-2.197) 13(-6.8,2.197) 14(-6.8,-2.197) 15(-6,2.197) 16(-6,-2.197) 17(-5.2,2.197) 18(-5.2,-2.197) 19(-4.4,2.197) 20(-4.4,-2.197) 21(-3.6,2.197) 22(-3.6,-2.197) 23(-2.8,2.197) 24(-2.8,-2.197) 25(-2,2.197) 26(-2,-2.197) 27(-1.2,2.197) 28(-1.2,-2.197) 29(-0.4,2.197) 30(-0.4,-2.197) 31(0.4,2.197) 32(0.4,-2.197) 33(1.2,2.197) 34(1.2,-2.197) 35(2,2.197) 36(2,-2.197) 37(2.8,2.197) 38(2.8,-2.197) 39(3.6,2.197) 40(3.6,-2.197) 41(4.4,2.197) 42(4.4,-2.197) 43(5.2,2.197) 44(5.2,-2.197) 45(6,2.197) 46(6,-2.197) 47(6.8,2.197) 48(6.8,-2.197) 49(7.6,2.197) 50(7.6,-2.197) 51(8.4,2.197) 52(8.4,-2.197) 53(9.2,2.197) 54(9.2,-2.197) 55(10,2.197) 56(10,-2.197) 57(10.8,2.197) 58(10.8,-2.197) 59(11.6,2.197) 60(11.6,-2.197)
CNHDR2X30H202
  round 2.286 hole 1.016 unplated: (-10.063,2.667) (10.063,2.667)
  rect 0.279x2.286 smd: 1(-7.264,-2.865) 2(-7.264,2.865) 3(-6.764,-2.865) 4(-6.764,2.865) 5(-6.264,-2.865) 6(-6.264,2.865) 7(-5.763,-2.865) 8(-5.763,2.865) 9(-5.263,-2.865) 10(-5.263,2.865) 11(-4.763,-2.865) 12(-4.763,2.865) 13(-4.262,-2.865) 14(-4.262,2.865) 15(-3.762,-2.865) 16(-3.762,2.865) 17(-3.261,-2.865) 18(-3.261,2.865) 19(-2.761,-2.865) 20(-2.761,2.865) 21(-2.261,-2.865) 22(-2.261,2.865) 23(-1.76,-2.865) 24(-1.76,2.865) 25(-1.26,-2.865) 26(-1.26,2.865) 27(-0.759,-2.865) 28(-0.759,2.865) 29(-0.259,-2.865) 30(-0.259,2.865) 31(0.241,-2.865) 32(0.241,2.865) 33(0.742,-2.865) 34(0.742,2.865) 35(1.242,-2.865) 36(1.242,2.865) 37(1.742,-2.865) 38(1.742,2.865) 39(2.243,-2.865) 40(2.243,2.865) 41(2.743,-2.865) 42(2.743,2.865) 43(3.244,-2.865) 44(3.244,2.865) 45(3.744,-2.865) 46(3.744,2.865) 47(4.244,-2.865) 48(4.244,2.865) 49(4.745,-2.865) 50(4.745,2.865) 51(5.245,-2.865) 52(5.245,2.865) 53(5.745,-2.865) 54(5.745,2.865) 55(6.246,-2.865) 56(6.246,2.865) 57(6.746,-2.865) 58(6.746,2.865) 59(7.247,-2.865) 60(7.247,2.865)
  rect 2.54x0.432 smd: PAD1(-8.065,0) PAD4(8.065,0)
  rect 4.699x0.432 smd: PAD2(-3.175,0) PAD3(3.175,0)
CNSMMHDR2X20L1571W157H272
  rect 0.991x2.743 smd: 1(-19,2.129) 2(-19,-2.129) 3(-17,2.129) 4(-17,-2.129) 5(-15,2.129) 6(-15,-2.129) 7(-13,2.129) 8(-13,-2.129) 9(-11,2.129) 10(-11,-2.129) 11(-9,2.129) 12(-9,-2.129) 13(-7,2.129) 14(-7,-2.129) 15(-5,2.129) 16(-5,-2.129) 17(-3,2.129) 18(-3,-2.129) 19(-1,2.129) 20(-1,-2.129) 21(1,2.129) 22(1,-2.129) 23(3,2.129) 24(3,-2.129) 25(5,2.129) 26(5,-2.129) 27(7,2.129) 28(7,-2.129) 29(9,2.129) 30(9,-2.129) 31(11,2.129) 32(11,-2.129) 33(13,2.129) 34(13,-2.129) 35(15,2.129) 36(15,-2.129) 37(17,2.129) 38(17,-2.129) 39(19,2.129) 40(19,-2.129)
CNTE1-1734248-5
  rect 0.61x1.651 smd: 1(-7,-1.876) 2(-6,-1.876) 3(-5,-1.876) 4(-4,-1.876) 5(-3,-1.876) 6(-2,-1.876) 7(-1,-1.876) 8(0,-1.876) 9(1,-1.876) 10(2,-1.876) 11(3,-1.876) 12(4,-1.876) 13(5,-1.876) 14(6,-1.876) 15(7,-1.876)
  rect 0.61x1.854 smd: 16(7,1.876) 17(6,1.876) 18(5,1.876) 19(4,1.876) 20(3,1.876) 21(2,1.876) 22(1,1.876) 23(0,1.876) 24(-1,1.876) 25(-2,1.876) 26(-3,1.876) 27(-4,1.876) 28(-5,1.876) 29(-6,1.876) 30(-7,1.876)
DO214AC
  rect 1.778x2.159 smd: A(2.032,0) C(-2.032,0)
DSML110W70H39
  rect 0.889x1.397 smd: A(1.605,0)
  rect 2.21x1.397 smd: C(-0.945,0)
L0402
  rect 0.584x0.711 smd: 1(-0.475,0) 2(0.475,0)
L0603
  rect 0.94x0.991 smd: 1(-0.8,0) 2(0.8,0)
L0805
  rect 1.194x1.448 smd: 1(-0.85,0) 2(0.85,0)
LED0603
  rect 0.965x0.762 smd: A(0.8,0) C(-0.8,0)
LED1206
  rect 1.499x1.499 smd: A(1.749,0) C(-1.749,0)
LSML75W79H39
  rect 1.041x2.21 smd: 1(-0.724,0) 2(0.724,0)
LSML250W258H240
  rect 1.422x5.334 smd: 1(-2.019,0) 2(2.019,0)
LSMSQ157H122
  rect 0.965x3.708 smd: 1(-1.181,0) 2(1.181,0)
MLP8_3X3_PAD2_3X1_4
  oval 0.305x0.914 smd: 1(-0.975,-1.557) 2(-0.325,-1.557) 3(0.325,-1.557) 4(0.975,-1.557) 5(0.975,1.557) 6(0.325,1.557) 7(-0.325,1.557) 8(-0.975,1.557)
  rect 2.311x1.397 smd: PAD(0,0)
MSOP8_ALT
  rect 0.406x1.194 smd: 1(-0.975,-2.05) 2(-0.325,-2.05) 3(0.325,-2.05) 4(0.975,-2.05) 5(0.975,2.05) 6(0.325,2.05) 7(-0.325,2.05) 8(-0.975,2.05)
QFN20_4X4_PAD2_6X2_6
  oval 0.305x1.041 smd: 1(-1,-2.019) 2(-0.5,-2.019) 3(0,-2.019) 4(0.5,-2.019) 5(1,-2.019) 11(1,2.019) 12(0.5,2.019) 13(0,2.019) 14(-0.5,2.019) 15(-1,2.019)
  oval 1.041x0.305 smd: 6(2.019,-1) 7(2.019,-0.5) 8(2.019,0) 9(2.019,0.5) 10(2.019,1) 16(-2.019,1) 17(-2.019,0.5) 18(-2.019,0) 19(-2.019,-0.5) 20(-2.019,-1)
  rect 2.591x2.591 smd: PAD(0,0)
QFN24_3_4X2_5
  rect 0.229x0.66 smd: 1(-1,-1.07)
  rect 0.229x0.559 smd: 2(-0.6,-1.121) 3(-0.2,-1.121) 4(0.2,-1.121) 5(0.6,-1.121) 6(1,-1.121) 13(1,1.121) 14(0.6,1.121) 15(0.2,1.121) 16(-0.2,1.121) 17(-0.6,1.121) 18(-1,1.121)
  rect 0.559x0.229 smd: 7(1.57,-1) 8(1.57,-0.6) 9(1.57,-0.2) 10(1.57,0.2) 11(1.57,0.6) 12(1.57,1) 19(-1.57,1) 20(-1.57,0.6) 21(-1.57,0.2) 22(-1.57,-0.2) 23(-1.57,-0.6) 24(-1.57,-1)
QFN24_4X4_PAD2_1X2_1
  oval 0.305x0.991 smd: 1(-1.25,-2) 2(-0.75,-2) 3(-0.25,-2) 4(0.25,-2) 5(0.75,-2) 6(1.25,-2) 13(1.25,2) 14(0.75,2) 15(0.25,2) 16(-0.25,2) 17(-0.75,2) 18(-1.25,2)
  oval 0.991x0.305 smd: 7(2,-1.25) 8(2,-0.75) 9(2,-0.25) 10(2,0.25) 11(2,0.75) 12(2,1.25) 19(-2,1.25) 20(-2,0.75) 21(-2,0.25) 22(-2,-0.25) 23(-2,-0.75) 24(-2,-1.25)
  rect 2.108x2.108 smd: PAD(0,0)
QFN28_5X4_PAD3_65X2_65
  oval 0.279x0.737 smd: 1(-1.75,-1.893) 2(-1.25,-1.893) 3(-0.75,-1.893) 4(-0.25,-1.893) 5(0.25,-1.893) 6(0.75,-1.893) 7(1.25,-1.893) 8(1.75,-1.893) 15(1.75,1.893) 16(1.25,1.893) 17(0.75,1.893) 18(0.25,1.893) 19(-0.25,1.893) 20(-0.75,1.893) 21(-1.25,1.893) 22(-1.75,1.893)
  oval 0.737x0.279 smd: 9(2.393,-1.25) 10(2.393,-0.75) 11(2.393,-0.25) 12(2.393,0.25) 13(2.393,0.75) 14(2.393,1.25) 23(-2.393,1.25) 24(-2.393,0.75) 25(-2.393,0.25) 26(-2.393,-0.25) 27(-2.393,-0.75) 28(-2.393,-1.25)
  rect 3.658x2.642 smd: PAD(0,0)
QFN38_7_8X7_4
  rect 1.219x1.219 smd: 1(-3.612,-3.412) 11(3.612,-3.412) 20(3.612,3.412) 30(-3.612,3.412)
  oval 0.406x1.295 smd: 2(-2.6,-3.45) 3(-1.95,-3.45) 4(-1.3,-3.45) 5(-0.65,-3.45) 6(0,-3.45) 7(0.65,-3.45) 8(1.3,-3.45) 9(1.95,-3.45) 10(2.6,-3.45) 21(2.6,3.45) 22(1.95,3.45) 23(1.3,3.45) 24(0.65,3.45) 25(0,3.45) 26(-0.65,3.45) 27(-1.3,3.45) 28(-1.95,3.45) 29(-2.6,3.45)
  oval 1.295x0.406 smd: 12(3.65,-2.275) 13(3.65,-1.625) 14(3.65,-0.975) 15(3.65,-0.325) 16(3.65,0.325) 17(3.65,0.975) 18(3.65,1.625) 19(3.65,2.275) 31(-3.65,2.275) 32(-3.65,1.625) 33(-3.65,0.975) 34(-3.65,0.325) 35(-3.65,-0.325) 36(-3.65,-0.975) 37(-3.65,-1.625) 38(-3.65,-2.275)
R0201
  rect 0.305x0.406 smd: 1(-0.318,0) 2(0.318,0)
R0402
  rect 0.635x0.737 smd: 1(-0.5,0) 2(0.5,0)
R0603
  rect 0.787x0.991 smd: 1(-0.85,0) 2(0.85,0)
R0603H35
  rect 0.813x0.813 smd: 1(-0.907,0) 2(0.907,0)
R0805
  rect 1.041x1.397 smd: 1(-0.95,0) 2(0.95,0)
R1206
  rect 1.041x1.753 smd: 1(-1.5,0) 2(1.5,0)
SC70
  rect 0.406x0.508 smd: 1(-0.65,-0.95) 2(0,-0.95) 3(0.65,-0.95) 4(0.65,0.95) 5(0,0.95) 6(-0.65,0.95)
SO8
  rect 0.61x2.184 smd: 1(-1.905,-2.54) 2(-0.635,-2.54) 3(0.635,-2.54) 4(1.905,-2.54) 5(1.905,2.54) 6(0.635,2.54) 7(-0.635,2.54) 8(-1.905,2.54)
SOD128
  rect 0.991x1.93 smd: A(2.21,0) C(-2.21,0)
SOD323-4
  rect 0.635x0.838 smd: A(1.118,0) C(-1.118,0)
SOD523
  rect 0.457x0.406 smd: A(0.679,0) C(-0.679,0)
SOT-963
  rect 0.203x0.203 smd: 1(-0.35,-0.45) 2(0,-0.45) 3(0.35,-0.45) 4(0.35,0.45) 5(0,0.45) 6(-0.35,0.45)
SWSML213W98H98
  rect 0.991x1.295 smd: 1(-1.75,-1.948) 2(0,1.948) 3(1.75,-1.948)
SWSML236W138H197
  rect 1.803x1.6 smd: 1(-2.702,0) 2(2.702,0)
SWSML291W220H83
  rect 0.762x1.27 smd: 1(-2.54,-3.81) 2(-1.27,-3.81) 3(0,-3.81) 4(1.27,-3.81) 5(2.54,-3.81) 6(2.54,3.81) 7(1.27,3.81) 8(0,3.81) 9(-1.27,3.81) 10(-2.54,3.81)
SWTHL500W272H280
  round 2.794 hole 1.499 unplated: (-1.905,9.525) (11.303,9.525)
  rect 2.286x2.286 hole 1.778: 1(0,0)
  round 2.286 hole 1.778: 2(4.699,0) 3(9.398,0)
TSSOP8
  rect 0.33x1.651 smd: 1(-0.975,-2.92) 2(-0.325,-2.92) 3(0.325,-2.92) 4(0.975,-2.92) 5(0.975,2.92) 6(0.325,2.92) 7(-0.325,2.92) 8(-0.975,2.92)
unnamed#2
  round 1.016 smd: (0,0)
unnamed#3
  round 1 hole 1.45 unplated: (-8.7,0) (8.7,0)
  round 0.5 hole 1.02 unplated: (-7.4,2.5) (7.4,-2.5)
UQFN6_1_6X1_6PAD0_5X1_05
  oval 0.254x0.813 smd: 1(-0.5,-0.907) 2(0,-0.907) 3(0.5,-0.907) 4(0.5,0.907) 5(0,0.907) 6(-0.5,0.907)
  rect 1.041x0.508 smd: PAD(0,0)
WLCSP6_B
  round 0.203 smd: A1(-0.4,-0.2) A2(-0.4,0.2) B1(0,-0.2) B2(0,0.2) C1(0.4,-0.2) C2(0.4,0.2)
WLCSP117_A
  round 0.254 smd: A2(-2.5,-2) A3(-2.5,-1.5) A4(-2.5,-1) A5(-2.5,-0.5) A6(-2.5,0) A7(-2.5,0.5) A8(-2.5,1) A9(-2.5,1.5) A10(-2.5,2) B1(-2,-2.5) B2(-2,-2) B3(-2,-1.5) B4(-2,-1) B5(-2,-0.5) B6(-2,0) B7(-2,0.5) B8(-2,1) B9(-2,1.5) B10(-2,2) B11(-2,2.5) C1(-1.5,-2.5) C2(-1.5,-2) C3(-1.5,-1.5) C4(-1.5,-1) C5(-1.5,-0.5) C6(-1.5,0) C7(-1.5,0.5) C8(-1.5,1) C9(-1.5,1.5) C10(-1.5,2) C11(-1.5,2.5) D1(-1,-2.5) D2(-1,-2) D3(-1,-1.5) D4(-1,-1) D5(-1,-0.5) D6(-1,0) D7(-1,0.5) D8(-1,1) D9(-1,1.5) D10(-1,2) D11(-1,2.5) E1(-0.5,-2.5) E2(-0.5,-2) E3(-0.5,-1.5) E4(-0.5,-1) E5(-0.5,-0.5) E6(-0.5,0) E7(-0.5,0.5) E8(-0.5,1) E9(-0.5,1.5) E10(-0.5,2) E11(-0.5,2.5) F1(0,-2.5) F2(0,-2) F3(0,-1.5) F4(0,-1) F5(0,-0.5) F6(0,0) F7(0,0.5) F8(0,1) F9(0,1.5) F10(0,2) F11(0,2.5) G1(0.5,-2.5) G2(0.5,-2) G3(0.5,-1.5) G4(0.5,-1) G5(0.5,-0.5) G6(0.5,0) G7(0.5,0.5) G8(0.5,1) G9(0.5,1.5) G10(0.5,2) G11(0.5,2.5) H1(1,-2.5) H2(1,-2) H3(1,-1.5) H4(1,-1) H5(1,-0.5) H6(1,0) H7(1,0.5) H8(1,1) H9(1,1.5) H10(1,2) H11(1,2.5) J1(1.5,-2.5) J2(1.5,-2) J3(1.5,-1.5) J4(1.5,-1) J5(1.5,-0.5) J6(1.5,0) J7(1.5,0.5) J8(1.5,1) J9(1.5,1.5) J10(1.5,2) J11(1.5,2.5) K1(2,-2.5) K2(2,-2) K3(2,-1.5) K4(2,-1) K5(2,-0.5) K6(2,0) K7(2,0.5) K8(2,1) K9(2,1.5) K10(2,2) K11(2,2.5) L2(2.5,-2) L3(2.5,-1.5) L4(2.5,-1) L5(2.5,-0.5) L6(2.5,0) L7(2.5,0.5) L8(2.5,1) L9(2.5,1.5) L10(2.5,2)
YSML98W79H35
  rect 1.092x0.991 smd: 1(-0.921,-0.72) 2(0.921,-0.72) 3(0.921,0.72) 4(-0.921,0.72)

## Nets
5V_LD: C97.1 C98.1 P21.27 P21.29 P21.31 P21.33 P21.35 P21.37 P21.39 R15.1 R16.1 R39.2(N2) R95.2(N2) U2.16(VIN) U2.19 U2.20
5VCC: C49.2(N2) E2.2(N2) E3.1 R17.1 R35.1 R37.1 R44.1 R75.1 R85.1
9VDD: C12.1 C15.1 Q1.4(E2) R9.1 R26.1 R59.2(N2) R71.2(N2) R104.1 U4.K10
GND: A1.2(VEE) A1.PAD C1.1 C2.2(N2) C3.1 C4.2(N2) C5.2(N2) C6.2(N2) C7.2(N2) C8.2(N2) C9.1 C10.2(N2) C11.2(N2) C12.2(N2) C13.2(N2) C14.2(N2) C15.2(N2) C16.2(N2) C17.2(N2) C18.2(N2) C19.2(N2) C20.1 C22.2(N2) C23.2(N2) C24.2(N2) C25.2(N2) C26.2(N2) C27.2(N2) C28.2(N2) C29.1 C30.2(N2) C31.2(N2) C33.2(N2) C37.1 C41.2(N2) C42.2(N2) C43.2(N2) C44.2(N2) C45.2(N2) C46.2(N2) C47.2(N2) C48.2(N2) C49.1 C50.1 C51.2(N2) C52.2(N2) C53.1 C54.2(N2) C55.2(N2) C56.1 C57.1 C58.2(N2) C60.2(N2) C61.2(N2) C62.1 C63.1 C64.2(N2) C65.2(N2) C66.2(N2) C67.1 C68.2(N2) C69.1 C70.1 C71.2(N2) C72.2(N2) C74.2(N2) C75.2(N2) C76.2(N2) C77.1 C78.2(N2) C79.2(N2) C80.2(N2) C81.2(N2) C82.1 C83.1 C84.2(N2) C85.2(N2) C86.1 C87.1 C88.1 C89.2(N2) C90.2(N2) C91.1 C92.2(N2) C93.2(N2) C94.2(N2) C95.2(N2) C96.2(N2) C97.2(N2) C98.2(N2) D1.A(P) D6.C DS1.C DS2.C DS3.C L8.1 P1.1 P1.4 P1.7 P1.10 P3.6 P3.12 P3.13 P3.18(N9) P3.19 P3.24 P3.25 P3.30 P3.31 P3.37 P3.40 P3.43 P3.46 P3.49 P3.52 P3.55 P3.58 P4.1 P4.2 P4.39 P4.40 P21.30 P21.34 P21.38 P21.42 P21.46 P21.50 P21.54 P21.58 P21.PAD1 P21.PAD2 P21.PAD3 P21.PAD4 P31.2 P31.3(N4) Q2.1 Q2.4(E) R2.1 R12.2(N2) R14.2(N2) R18.1 R20.2(N2) R23.2(N2) R27.2(N2) R29.2(N2) R36.1 R38.2(N2) R48.2(N2) R54.1 R57.2(N2) R60.1 R63.1 R73.1 R84.2(N2) R90.1 R99.2(N2) R103.1 R106.1 R112.2(N2) RT1.1 U1.6 U1.20 U1.22 U1.24 U1.29 U2.1 U2.6 U2.11 U2.17 U2.22 U2.PAD U3.1 U3.2 U3.5 U3.14 U3.18 U3.23 U3.24 U3.PAD U4.B2 U4.B3 U4.B5 U4.B7 U4.B9 U4.C2 U4.C3 U4.C5 U4.C7 U4.C9 U4.C10 U4.D2 U4.D3 U4.D6 U4.D9 U4.D10 U4.E2 U4.E4 U4.E9 U4.E10 U4.G2 U4.G10 U4.H10 U4.J10 U4.K2 U4.L6 U5.4 U6.4 U6.5 U6.PAD U7.9 U8.4 U9.4 U10.2 U10.13 U10.19 U10.PAD U11.9 U12.C2 U13.7 U14.4 Y1.2
V1: U1.37 U4.J9
V2: U1.3 U4.J8
V3: U1.36 U4.H7
V4: U1.4 U4.L10
V9: U1.2 U4.J7
V10: U1.13 U4.K8
V11: U1.14 U4.H5
V12: U1.35 U4.L8
V13: U1.8 U4.K7
V14: U1.11 U4.J6
V15: U1.9 U4.K6
V16: U1.5 U4.L7
VCC: C37.2(N2) D2.C R107.1 U2.8 U2.12 U2.13
1P8VDD: C6.1 C14.1 C17.1 C19.1 C22.1 C23.1 C25.1 C28.1 C77.2(N2) C82.2(N2) C83.2(N2) D4.A(P) E1.2(N2) R34.2(N2) R72.2(N2) R119.2(N2) U4.A6 U4.B1 U4.B6 U4.B11 U4.E1 U4.G3 U4.H11 U4.K1 U4.L5
2P1VDD: C45.1 R32.2(N2) U3.21
3P3VDD: C10.1 C11.1 C13.1 C16.1 C26.1 C31.1 C54.1 C58.1 C60.1 C61.1 R65.2(N2) U4.A2 U4.A4 U4.A8 U4.A10 U4.D1 U4.D11 U4.E11 U4.G11 U4.J11
3P5VDD: C1.2(N2) C53.2(N2) C56.2(N2) C68.1 C69.2(N2) C75.1 C86.2(N2) C87.2(N2) C89.1 P21.9 R4.1 R22.2(N2) R24.1 R74.1 R81.2(N2) R82.1 R83.2(N2) R91.2(N2) R93.2(N2) R94.2(N2) R101.2(N2) R102.2(N2) R105.2(N2) R120.1 S5.1 U4.C1 U7.10(VCC) U8.8(VCC(B)) U9.8(VCC(B)) U11.10(VCC) U13.8(VDD) U14.8(VCC(B))
3P5VDD_RPI: C67.2(N2) P1.15 S5.10
AFE_GPO1: U1.33 U4.G9
AFE_GPO2: U4.G8
AFE_GPO3: R96.2(N2) R114.2(N2) U4.F3
AFE_GPO4: R92.2(N2) R116.2(N2) U4.H4
AFE_GPO5: U4.L4
AFE_GPO6: R118.2(N2) U4.K4
AFE_GPO7: LD_EN1.2(S2) U4.J4
AFE_GPO8: LD_EN2.2(S2) U4.J5
AFETEMP_I2C1_SCL: R82.2(N2) U8.7 U13.1
AFETEMP_I2C1_SDA: R74.2(N2) U8.6 U13.2
CCDINA: C21.2(N2) U4.B10
CLI: R110.2(N2) U4.C6
CLK_N: U4.J3 U7.2
CLK_P: U4.J2 U7.1
DATA0_N: U4.J1 U7.4
DATA0_P: U4.H1 U7.3
DATA1_N: U4.H2 U7.6
DATA1_P: U4.H3 U7.5
FB: R11.2(N2) R12.1 U2.9
H1: U1.28 U4.F10
H2: U1.27 U4.F11
HD: U4.F2
HL: R66.1 U4.H9
I2C2_SCL: P3.32 R41.1 R43.2(N2) S5.2 S5.3 U14.2
I2C2_SDA: P3.34 R6.1 R45.2(N2) S5.4 S5.5 U14.3
I2C_RPI_SCL: R83.1 R98.1 U14.7
I2C_RPI_SDA: R81.1 R109.1 U14.6
IOVDD: C33.1 C52.1 C63.2(N2) C70.2(N2) C88.2(N2) P21.15 R43.1 R45.1 R47.2(N2) R55.2(N2) R61.2(N2) R62.2(N2) R64.2(N2) R67.2(N2) R68.2(N2) R77.1 R80.1 R86.1 R87.1 R119.1 R120.2(N2) U4.G1 U5.8 U8.1 U9.1 U14.1
LASERTEMP_I2C1_SCL: P21.5 R94.1 U9.7
LASERTEMP_I2C1_SDA: P21.7 R93.1 U9.6
LD1: P21.60 U4.A3
LD2: P21.52 U4.A5
LD3: P21.44 U4.A7
LD4: P21.36 U4.A9
LD5: R5.1 U4.C11
LD_EN1: LD_EN1.1 P21.1
LD_EN2: LD_EN2.1 P21.3
LED_BLUE: P4.8 R78.1
LED_RED: P4.10 R79.1
LS_I2C0_SCL: P4.15 R61.1 S5.8 U5.6
LS_I2C0_SDA: P4.17 R64.1 S5.6 U5.5
LS_I2C1_SCL: P4.19 R68.1 S5.9(N9) U8.2 U9.2
LS_I2C1_SDA: P4.21 R67.1 S5.7 U8.3 U9.3
MIPI_CSI0_CLK_N: P3.4 U11.16
MIPI_CSI0_CLK_P: P3.2 U11.17
MIPI_CSI0_DATA0_N: P3.10 U11.14
MIPI_CSI0_DATA0_P: P3.8 U11.15
MIPI_CSI0_DATA1_N: P3.16 U11.12
MIPI_CSI0_DATA1_P: P3.14 U11.13
MIPI_CSI1_CLK_M: P3.56 U7.16
MIPI_CSI1_CLK_P: P3.54 U7.17
MIPI_CSI1_DATA0_M: P3.44 U7.14
MIPI_CSI1_DATA0_P: P3.42 U7.15
MIPI_CSI1_DATA1_M: P3.50 U7.12
MIPI_CSI1_DATA1_P: P3.48 U7.13
PGOOD: R16.2(N2) U2.7
PVOUT: C90.1 C92.1 C93.1 C94.1 C95.1 C96.1 D2.A(P) R11.1 R25.2(N2) U2.3 U2.4
PWM_SYNC: R107.2(N2) R112.1 U2.25
REFB: C8.1 U4.D8
REFT: C2.1 U4.D7
RG: R69.1 U4.H8
RPI_CLKN: P1.8 U11.2
RPI_CLKP: P1.9(N9) U11.1
RPI_DATA0N: P1.2 U11.4
RPI_DATA0P: P1.3 U11.3
RPI_DATA1N: P1.5 U11.6
RPI_DATA1P: P1.6 U11.5
RPI_SRS_CLKN: U7.23 U11.23
RPI_SRS_CLKP: U7.22 U11.22
RPI_SRS_DATA0N: U7.21 U11.21
RPI_SRS_DATA0P: U7.20 U11.20
RPI_SRS_DATA1N: U7.18 U11.18
RPI_SRS_DATA1P: U7.19 U11.19
RSTB_SYNC: C24.1 P4.23 U4.G4
RUN: R115.2(N2) R116.1 U2.15
SEL: S1.2 U7.11 U11.11
SPI1_CLK: R28.1 R113.1
SPI1_CS_N: P3.7 R89.2(N2)
SPI1_MISO: P3.1 R88.2(N2)
SPI1_MOSI: P3.11 R3.1
SUB: C59.2(N2) D4.C D5.C R29.1 R42.1 U1.15 U1.16
SUBOUT: R7.1 U1.18
SW1: C38.2(N2) L1.2(N2) U2.18 U2.21
SW2: C35.1 L1.1 U2.2 U2.5
TAL1: P21.56 U4.C4
TAL2: P21.48 U4.B4
TAL3: P21.40 U4.B8
TAL4: P21.32 U4.C8
TAL5: R40.1 R42.2(N2) U4.E8
TAVDD: C7.1 R65.1 U4.E6
TEMP_CT_AFE: P4.24 R87.2(N2) U13.6
TEMP_CT_LASER: P4.25 P21.11
TEMP_INT_AFE: P4.26 R86.2(N2) U13.5
TEMP_INT_LASER: P4.27 P21.13
UNNAMED_5_ADP5023_I567_AVIN: C3.2(N2) C4.1 C9.2(N2) R17.2(N2) R97.1 U3.3 U3.7 U3.12 U3.16 U3.17 U3.22
UNNAMED_5_ADP5023_I567_FB1: R23.1 R30.1 U3.11
UNNAMED_5_ADP5023_I567_FB2: R20.1 R21.1 U3.8
UNNAMED_5_ADP5023_I567_FB3: R18.2(N2) R19.1 U3.19
UNNAMED_5_ADP5023_I567_MODE: R97.2(N2) R99.1 U3.13
UNNAMED_5_ADP5023_I567_SW1: L2.2(N2) U3.15
UNNAMED_5_ADP5023_I567_SW2: L3.2(N2) U3.4
UNNAMED_5_ADP5023_I567_VOUT1: C48.1 L2.1 R22.1 R30.2(N2) U3.10
UNNAMED_5_ADP5023_I567_VOUT2: C47.1 L3.1 R21.2(N2) R32.1 U3.9
UNNAMED_5_ADP5023_I567_VOUT3: C46.1 R19.2(N2) R34.1 U3.20(VOUT3)
UNNAMED_5_ADP5071_I420_COMP1: R50.1 U10.6
UNNAMED_5_ADP5071_I420_COMP2: R51.1 U10.10
UNNAMED_5_ADP5071_I420_EN1: R35.2(N2) R92.1 U10.7
UNNAMED_5_ADP5071_I420_EN2: R85.2(N2) R96.1 U10.9
UNNAMED_5_ADP5071_I420_FB1: R48.1 R52.1 U10.5
UNNAMED_5_ADP5071_I420_FB2: R46.2(N2) R49.1 U10.11
UNNAMED_5_ADP5071_I420_INBK: L9.1 U10.1
UNNAMED_5_ADP5071_I420_PVIN1: C41.1 R44.2(N2) U10.15 U10.16 U10.17
UNNAMED_5_ADP5071_I420_SW1: D9.A(P) L9.2(N2) U10.20
UNNAMED_5_ADP5071_I420_SW2: D8.C L8.2(N2) U10.18
UNNAMED_5_ADP5071_I420_VREF: C43.1 R46.1 U10.12
UNNAMED_5_ADP5071_I420_VREG: C66.1 U10.14(VREG)
UNNAMED_5_ADP7112_I458_EN: R38.1 R111.2(N2) R114.1 U12.C1
UNNAMED_5_ADP7112_I458_SENSE: R57.1 R58.1 U12.B2
UNNAMED_5_ADP7112_I458_SS: C80.1 U12.B1
UNNAMED_5_ADP7112_I458_VIN: C79.1 R56.2(N2) U12.A1
UNNAMED_5_ADP7112_I458_VOUT: C81.1 R58.2(N2) R59.1 U12.A2(VOUT)
UNNAMED_5_CAP_I59_N2: C50.2(N2) E3.2(N2) R95.1
UNNAMED_5_CAP_I499_N1: C71.1 D8.A(P) E4.1 R49.2(N2)
UNNAMED_5_CAP_I500_N1: C78.1 D9.C R8.1 R52.2(N2)
UNNAMED_5_CAP_I511_N1: C42.1 E2.1 R100.2(N2) S2.2
UNNAMED_5_CAP_I516_N1: C72.1 R50.2(N2)
UNNAMED_5_CAP_I517_N1: C74.1 R51.2(N2)
UNNAMED_5_CAP_I691_N1: C38.1 U2.23
UNNAMED_5_CAP_I700_N2: C35.2(N2) U2.28
UNNAMED_5_CAP_I722_N2: C91.2(N2) R13.1
UNNAMED_5_CN4PV6_I401_N1: D1.C P31.1A P31.1B S2.1
UNNAMED_5_DIOLED_I652_P: DS1.A(P) R100.1
UNNAMED_5_DIOLED_I662_P: DS2.A(P) R104.2(N2)
UNNAMED_5_DIOLED_I714_P: DS3.A(P) R108.1
UNNAMED_5_FERRITE_I642_N2: E4.2(N2) R53.1
UNNAMED_5_LINLTC3119_I686_RT: R14.1 U2.14
UNNAMED_5_LINLTC3119_I686_VC: R13.2(N2) U2.10
UNNAMED_5_RES_I689_N2: R15.2(N2) R115.1
UNNAMED_6_CAP_I286_N1: C85.1 P4.28 S4.1
UNNAMED_6_CAP_I292_N1: C84.1 P4.29 S3.2(B)
UNNAMED_6_CN30PV2_I274_N13: P1.13 R98.2(N2)
UNNAMED_6_CN30PV2_I274_N14: P1.14 R109.2(N2)
UNNAMED_6_CN60PODDEVEN_I272_N5: P3.9 R113.2(N2)
UNNAMED_6_DIOLED_I296_N: DS5.C Q2.3
UNNAMED_6_DIOLED_I296_P: DS5.A(P) R75.2(N2)
UNNAMED_6_DIOLED_I301_N: DS4.C Q2.6
UNNAMED_6_DIOLED_I301_P: DS4.A(P) R37.2(N2)
UNNAMED_6_RES_I283_N2: R80.2(N2) S4.2(B)
UNNAMED_6_RES_I294_N2: R77.2(N2) S3.1
UNNAMED_6_RES_I297_N2: Q2.5 R79.2(N2)
UNNAMED_6_RES_I302_N2: Q2.2 R78.2(N2)
UNNAMED_7_ADA4800_I153_IN: A1.1 U1.21(VO)
UNNAMED_7_ADA4800_I153_OUT: A1.3 R76.1
UNNAMED_7_CAP_I99_N1: C30.1 D5.A(P) Q1.1 Q1.3 R27.1
UNNAMED_7_CAP_I107_N1: C18.1 Q1.2 R7.2(N2)
UNNAMED_7_CAP_I123_N2: A1.5 C62.2(N2) R9.2(N2) R31.2(N2) R33.2(N2)
UNNAMED_7_CAP_I131_N1: C51.1 D6.A(P) R70.1 U1.30
UNNAMED_7_CAP_I133_N1: C73.1 R69.2(N2)
UNNAMED_7_CAP_I133_N2: C73.2(N2) U1.23
UNNAMED_7_CAP_I138_N1: C59.1 R40.2(N2) U6.6 U6.7
UNNAMED_7_CAP_I142_N1: C76.1 R71.1 U1.19
